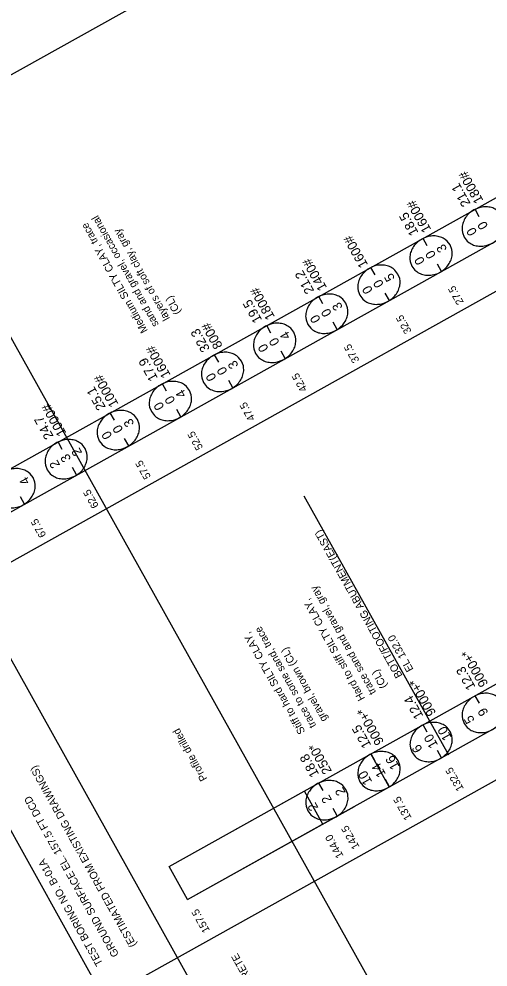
# Model space of a CAD drawing. Extents: x 13482447 to 13495412, y 324533 to 340229.
# Drawn here: x 13492545 to 13492842, y 330577 to 331177 of the extents above; entities that cross this region are included whole.
import ezdxf

# ---------------------------------------------------------------- set-up
doc = ezdxf.new("R2010")
doc.units = 0
for name, color, linetype in [('Default', 7, 'Continuous'), ('DETAIL_TEXT_DIMEN_PR', 7, 'Continuous'), ('Level 1', 7, 'Continuous'), ('Level 63', 7, 'Continuous'), ('TYPICAL_TEXT_DIMEN_PR', 7, 'Continuous')]:
    doc.layers.add(name, color=color, linetype=linetype)

# ---------------------------------------------------------------- blocks, each defined once
blk = doc.blocks.new('DGRFC_BLOW$COUNT$ELLIPSE')
at = {"layer": 'Default'}
blk.add_lwpolyline([(0, -0.0274), (0.0061, -0.0265), (0.0089, -0.0254), (0.0104, -0.0246), (0.0118, -0.0238), (0.0132, -0.0228), (0.0145, -0.0218), (0.0157, -0.0206), (0.0168, -0.0194), (0.0179, -0.018), (0.0189, -0.0167), (0.0198, -0.0152), (0.0206, -0.0137), (0.0213, -0.0122), (0.022, -0.0106), (0.023, -0.0071), (0.0236, -0.0036), (0.0238, 0), (0.0236, 0.0036), (0.023, 0.0071), (0.022, 0.0106), (0.0213, 0.0122), (0.0206, 0.0137), (0.0198, 0.0152), (0.0189, 0.0167), (0.0179, 0.018), (0.0168, 0.0194), (0.0157, 0.0206), (0.0145, 0.0218), (0.0132, 0.0228), (0.0118, 0.0238), (0.0104, 0.0246), (0.0089, 0.0254), (0.0061, 0.0265), (0, 0.0274), (-0.0061, 0.0265), (-0.0089, 0.0254), (-0.0104, 0.0246), (-0.0118, 0.0238), (-0.0132, 0.0228), (-0.0145, 0.0218), (-0.0157, 0.0206), (-0.0168, 0.0194), (-0.0179, 0.018), (-0.0189, 0.0167), (-0.0198, 0.0152), (-0.0206, 0.0137), (-0.0213, 0.0122), (-0.022, 0.0106), (-0.023, 0.0071), (-0.0236, 0.0036), (-0.0238, 0), (-0.0236, -0.0036), (-0.023, -0.0071), (-0.022, -0.0106), (-0.0213, -0.0122), (-0.0206, -0.0137), (-0.0198, -0.0152), (-0.0189, -0.0167), (-0.0179, -0.018), (-0.0168, -0.0194), (-0.0157, -0.0206), (-0.0145, -0.0218), (-0.0132, -0.0228), (-0.0118, -0.0238), (-0.0104, -0.0246), (-0.0089, -0.0254), (-0.0061, -0.0265), (0, -0.0274)], dxfattribs=at)

msp = doc.modelspace()

# ---------------------------------------------------------------- linework, layer by layer
at = {"layer": 'Default'}
for points in [[(13492832.27, 331304.34), (13492334.38, 331026.77)], [(13492503.84, 330872.1), (13493032.44, 331167.11)], [(13492515.49, 330851.24), (13493044.09, 331146.24)], [(13493088.01, 331138.85), (13492465.62, 330791.57)], [(13492639.99, 330640.22), (13493165.19, 330933.38)], [(13492651.68, 330619.26), (13493176.1, 330911.99)], [(13493219.69, 330902.86), (13492597.3, 330555.58)], [(13492779.38, 330690.57), (13492767.69, 330711.53)], [(13492639.99, 330640.22), (13492745.56, 330699.12)], [(13492737.34, 330667.05), (13492725.65, 330688.01)], [(13492651.68, 330619.26), (13492757.25, 330678.16)], [(13492651.68, 330619.26), (13492639.99, 330640.22)]]:
    msp.add_lwpolyline(points, dxfattribs=at)
at = {"layer": 'Level 1'}
msp.add_line((13492729.51, 330322.82), (13492088.28, 331472.03), dxfattribs=at)
at = {"layer": 'Level 63'}
msp.add_lwpolyline([(13492129.81, 329985.73), (13491486.63, 331138.43), (13492220.17, 331547.72), (13492863.35, 330395.02)], close=True, dxfattribs=at)
at = {"layer": 'TYPICAL_TEXT_DIMEN_PR'}
for p, q in [((13492776.8, 330346.93), (13492382.64, 331053.32)), ((13492836.33, 331051.53), (13492833.74, 331056.18)), ((13492803.34, 331033.13), (13492800.75, 331037.77)), ((13492812.4, 331016.9), (13492809.8, 331021.55)), ((13492770.35, 331014.72), (13492767.76, 331019.36)), ((13492779.41, 330998.5), (13492776.81, 331003.14)), ((13492737.36, 330996.31), (13492734.77, 331000.96)), ((13492746.42, 330980.09), (13492743.82, 330984.73)), ((13492704.37, 330977.9), (13492701.78, 330982.55)), ((13492671.38, 330959.5), (13492668.79, 330964.14)), ((13492713.43, 330961.68), (13492710.83, 330966.33)), ((13492638.39, 330941.09), (13492635.8, 330945.73)), ((13492680.44, 330943.27), (13492677.84, 330947.92)), ((13492605.4, 330922.68), (13492602.81, 330927.33)), ((13492647.45, 330924.87), (13492644.85, 330929.51)), ((13492572.42, 330904.27), (13492569.82, 330908.92)), ((13492614.46, 330906.46), (13492611.86, 330911.1)), ((13492581.47, 330888.05), (13492578.88, 330892.7)), ((13492548.48, 330869.64), (13492545.89, 330874.29)), ((13492817, 330710.6), (13492725.53, 330874.53)), ((13492836.39, 330743.65), (13492833.79, 330748.29)), ((13492803.4, 330725.24), (13492800.8, 330729.89)), ((13492770.41, 330706.83), (13492767.81, 330711.48)), ((13492812.45, 330709.02), (13492809.86, 330713.66)), ((13492737.42, 330688.43), (13492734.82, 330693.07)), ((13492779.46, 330690.61), (13492776.87, 330695.26)), ((13492746.47, 330672.2), (13492743.88, 330676.85))]:
    msp.add_line(p, q, dxfattribs=at)

# ---------------------------------------------------------------- block references
at = {"layer": 'Default', "xscale": 503.9370078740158, "yscale": 503.93700787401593, "rotation": 119.16052892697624}
for p in [(13492838.77, 331045.3), (13492838.77, 331045.3), (13492805.78, 331026.9), (13492805.78, 331026.9), (13492772.79, 331008.49), (13492772.79, 331008.49), (13492739.81, 330990.08), (13492739.81, 330990.08), (13492706.82, 330971.67), (13492706.82, 330971.67), (13492673.83, 330953.27), (13492673.83, 330953.27), (13492640.84, 330934.86), (13492640.84, 330934.86), (13492607.85, 330916.45), (13492607.85, 330916.45), (13492574.86, 330898.04), (13492574.86, 330898.04), (13492541.87, 330879.64), (13492541.87, 330879.64), (13492838.83, 330737.42), (13492838.83, 330737.42), (13492805.84, 330719.01), (13492805.84, 330719.01), (13492772.85, 330700.61), (13492772.85, 330700.61), (13492739.86, 330682.2), (13492739.86, 330682.2)]:
    msp.add_blockref('DGRFC_BLOW$COUNT$ELLIPSE', p, dxfattribs=at)

# ---------------------------------------------------------------- texts
at = {"layer": 'Default'}
for s, height, p in [('1800#', 5.952, (13492839.04, 331061.81)), ('1800#', 5.952, (13492839.04, 331061.81)), (' 21.1', 5.952, (13492832.06, 331057.92)), (' 21.1', 5.952, (13492832.06, 331057.92)), ('1600#', 5.952, (13492806.05, 331043.41)), ('1600#', 5.952, (13492806.05, 331043.41)), (' 18.5', 5.952, (13492799.07, 331039.51)), (' 18.5', 5.952, (13492799.07, 331039.51)), ('0', 5.95, (13492835.13, 331041.53)), ('0', 5.95, (13492835.13, 331041.53)), ('0', 5.95, (13492842.11, 331045.43)), ('0', 5.95, (13492842.11, 331045.43)), ('1600#', 5.952, (13492766.08, 331021.1)), ('1600#', 5.952, (13492766.08, 331021.1)), ('3', 5.95, (13492816.11, 331030.92)), ('3', 5.95, (13492816.11, 331030.92)), ('0', 5.95, (13492809.12, 331027.02)), ('0', 5.95, (13492809.12, 331027.02)), ('1400#', 5.952, (13492740.07, 331006.59)), ('1400#', 5.952, (13492740.07, 331006.59)), ('0', 5.95, (13492802.14, 331023.12)), ('0', 5.95, (13492802.14, 331023.12)), (' 21.2', 5.952, (13492733.09, 331002.69)), (' 21.2', 5.952, (13492733.09, 331002.69)), ('5', 5.95, (13492783.12, 331012.51)), ('5', 5.95, (13492783.12, 331012.51)), ('0', 5.95, (13492776.13, 331008.61)), ('0', 5.95, (13492776.13, 331008.61)), ('1800#', 5.952, (13492707.08, 330988.18)), ('1800#', 5.952, (13492707.08, 330988.18)), ('0', 5.95, (13492769.15, 331004.72)), ('0', 5.95, (13492769.15, 331004.72)), (' 19.5', 5.952, (13492700.1, 330984.28)), (' 19.5', 5.952, (13492700.1, 330984.28)), ('3', 5.95, (13492750.13, 330994.11)), ('3', 5.95, (13492750.13, 330994.11)), ('0', 5.95, (13492743.14, 330990.21)), ('0', 5.95, (13492743.14, 330990.21)), ('0', 5.95, (13492736.16, 330986.31)), ('0', 5.95, (13492736.16, 330986.31)), (' 32.3', 5.952, (13492667.11, 330965.88)), (' 32.3', 5.952, (13492667.11, 330965.88)), ('800#', 5.952, (13492674.09, 330969.78)), ('800#', 5.952, (13492674.09, 330969.78)), ('4', 5.95, (13492717.14, 330975.7)), ('4', 5.95, (13492717.14, 330975.7)), ('0', 5.95, (13492710.15, 330971.8)), ('0', 5.95, (13492710.15, 330971.8)), ('1600#', 5.952, (13492641.1, 330951.37)), ('1600#', 5.952, (13492641.1, 330951.37)), ('0', 5.95, (13492703.17, 330967.9)), ('0', 5.95, (13492703.17, 330967.9)), (' 17.9', 5.952, (13492634.12, 330947.47)), (' 17.9', 5.952, (13492634.12, 330947.47)), ('3', 5.95, (13492684.15, 330957.29)), ('3', 5.95, (13492684.15, 330957.29)), ('0', 5.95, (13492677.16, 330953.39)), ('0', 5.95, (13492677.16, 330953.39)), ('1000#', 5.952, (13492608.11, 330932.96)), ('1000#', 5.952, (13492608.11, 330932.96)), ('0', 5.95, (13492670.18, 330949.49)), ('0', 5.95, (13492670.18, 330949.49)), (' 25.1', 5.952, (13492601.13, 330929.06)), (' 25.1', 5.952, (13492601.13, 330929.06)), ('0', 5.95, (13492644.17, 330934.98)), ('0', 5.95, (13492644.17, 330934.98)), ('4', 5.95, (13492651.16, 330938.88)), ('4', 5.95, (13492651.16, 330938.88)), ('1000#', 5.952, (13492575.13, 330914.55)), ('1000#', 5.952, (13492575.13, 330914.55)), ('0', 5.95, (13492637.19, 330931.09)), ('0', 5.95, (13492637.19, 330931.09)), (' 24.7', 5.952, (13492568.14, 330910.65)), (' 24.7', 5.952, (13492568.14, 330910.65)), ('0', 5.95, (13492611.18, 330916.58)), ('0', 5.95, (13492611.18, 330916.58)), ('3', 5.95, (13492618.17, 330920.48)), ('3', 5.95, (13492618.17, 330920.48)), ('0', 5.95, (13492604.2, 330912.68)), ('0', 5.95, (13492604.2, 330912.68)), ('3', 5.95, (13492578.19, 330898.17)), ('3', 5.95, (13492578.19, 330898.17)), ('2', 5.95, (13492585.18, 330902.07)), ('2', 5.95, (13492585.18, 330902.07)), ('2', 5.95, (13492571.21, 330894.27)), ('2', 5.95, (13492571.21, 330894.27)), ('4', 5.95, (13492552.19, 330883.66)), ('4', 5.95, (13492552.19, 330883.66)), ('9000+*', 5.952, (13492842.14, 330755.87)), ('9000+*', 5.952, (13492842.14, 330755.87)), (' 12.3', 5.952, (13492835.15, 330751.97)), (' 12.3', 5.952, (13492835.15, 330751.97)), ('9000+*', 5.952, (13492809.15, 330737.46)), ('9000+*', 5.952, (13492809.15, 330737.46)), (' 12.4', 5.952, (13492802.16, 330733.56)), (' 12.4', 5.952, (13492802.16, 330733.56)), ('9000+*', 5.952, (13492776.16, 330719.05)), ('9000+*', 5.952, (13492776.16, 330719.05)), ('9', 5.95, (13492842.26, 330737.5)), ('5', 5.95, (13492833.6, 330732.67)), (' 12.5', 5.952, (13492769.17, 330715.15)), (' 12.5', 5.952, (13492769.17, 330715.15)), ('10', 5.952, (13492819.07, 330721.9)), ('10', 5.952, (13492810.4, 330717.07)), ('2500*', 5.952, (13492743.17, 330700.64)), ('2500*', 5.952, (13492743.17, 330700.64)), ('6', 5.95, (13492800.61, 330714.26)), (' 18.8', 5.952, (13492736.18, 330696.74)), (' 18.8', 5.952, (13492736.18, 330696.74)), ('16', 5.952, (13492786.08, 330703.49)), ('14', 5.952, (13492777.41, 330698.66)), ('10', 5.952, (13492768.75, 330693.82)), ('2', 5.95, (13492751.96, 330687.11)), ('2', 5.95, (13492743.29, 330682.28)), ('2', 5.95, (13492734.63, 330677.44))]:
    msp.add_text(s, height=height, rotation=119.16053, dxfattribs=at).set_placement(p)
at = {"layer": 'DETAIL_TEXT_DIMEN_PR'}
for s, p in [('sand and gravel, occasional ', (13492633.64, 330983.29)), ('Medium SILTY CLAY, trace ', (13492626.65, 330979.4)), ('layers of soft clay, gray ', (13492640.62, 330987.19)), ('27.5', (13492826.59, 330997.4)), ('(CL)', (13492647.61, 330991.09)), ('32.5', (13492793.6, 330978.99)), ('37.5', (13492760.61, 330960.58)), ('42.5', (13492727.62, 330942.17)), ('47.5', (13492694.63, 330923.77)), ('52.5', (13492661.64, 330905.36)), ('57.5', (13492628.65, 330886.95)), ('62.5', (13492595.66, 330868.54)), ('67.5', (13492562.44, 330850.01)), ('BOTT/FOOTING ABUTMENT(EAST)', (13492787.83, 330761.08)), ('trace sand and gravel, gray ', (13492771.16, 330750.56)), ('Hard to stiff SILTY CLAY, ', (13492764.18, 330746.66)), ('Stiff to hard SILTY CLAY, ', (13492726.34, 330725.55)), ('trace to some sand, trace ', (13492733.33, 330729.45)), ('EL 132.0', (13492794.81, 330764.98)), ('gravel, brown (CL)', (13492740.32, 330733.35)), ('(CL)', (13492778.15, 330754.46)), ('Profile drilled', (13492664.31, 330695.78)), ('(ESTIMATED FROM EXISTING DRAWINGS)', (13492619.52, 330590.7)), ('132.5', (13492826.64, 330689.51)), ('GROUND SURFACE EL. 157.5 FT DCD', (13492608.44, 330584.52)), ('137.5', (13492793.65, 330671.11)), ('142.5', (13492760.66, 330652.7)), ('144.0', (13492750.51, 330647.03)), ('TEST BORING NO. B-01A', (13492598.26, 330578.84)), ('157.5', (13492665.93, 330599.84)), ('8 inches of PORTLAND CEMENT CONCRETE', (13492748.8, 330468.26))]:
    msp.add_text(s, height=4.8, rotation=119.16053, dxfattribs=at).set_placement(p)

doc.saveas('drawing.dxf')
